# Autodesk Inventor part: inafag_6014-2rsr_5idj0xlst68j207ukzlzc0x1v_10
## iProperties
Shininess: 64.0
Angle Display Precision: 2
Document Length Units: 11269
Document Angle Units: 11279
Document Time Units: 11290
Document Mass Units: 11283
Document Length Units Precision: 3
Document Angle Units Precision: 2
Compacted: True
Created: 2008-08
Part Number: inafag_6014-2rsr_5idj0xlst68j207ukzlzc0x1v_10
Document SubType Name: Modeling
Designer: tpomodeler
Density: 0.0
Volumn: 0.0
Area: 0.0
PropertySet Name: Model Information
Control State: 0
Master: False
Checked Out: False
Author: tpomodeler
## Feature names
1. inafag_6014-2rsr_5idj0xlst68j207ukzlzc0x1v
